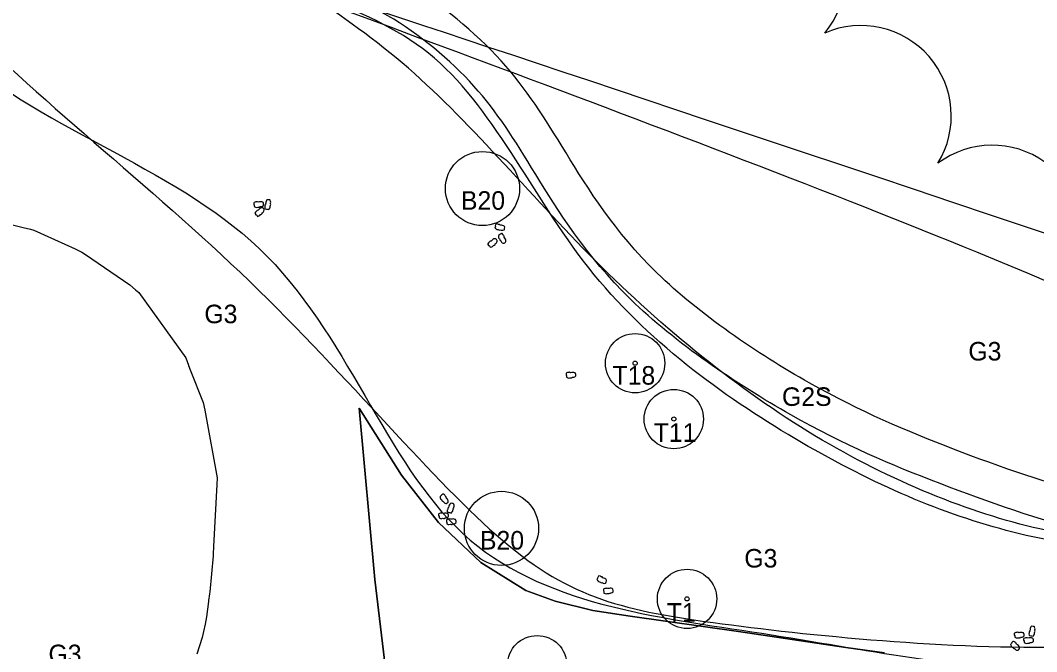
# Model space of a CAD drawing. Extents: x 0 to 512122, y 0 to 6212554.
# Drawn here: x 511501.5 to 511570.1, y 6211382.9 to 6211425.5 of the extents above; entities that cross this region are included whole.
import ezdxf

# ---------------------------------------------------------------- set-up
doc = ezdxf.new("R2010")
doc.units = 0
for name, color, linetype in [('_Marksten', 7, 'Continuous'), ('_Paths', 7, 'Continuous'), ('_S1_rabarber', 7, 'Continuous'), ('_Spredmingskorridor', 7, 'Continuous'), ('_Spredmingskorridor_hatch', 7, 'Continuous'), ('Clouds', 7, 'Continuous'), ('Skel', 7, 'Continuous'), ('TV_U_AFM_Symbl_Gul', 7, 'Continuous'), ('TV_U_LYS_Mastenummer', 7, 'Continuous'), ('TV_U_LYS_Nyx330-Trafiksti-x2', 7, 'Continuous')]:
    doc.layers.add(name, color=color, linetype=linetype)

# ---------------------------------------------------------------- blocks, each defined once
blk = doc.blocks.new('SOLITAIRE TREES')
at = {"layer": 'Skel'}
for radius in [2, 0.141]:
    blk.add_circle((0, 0), radius, dxfattribs=at)

msp = doc.modelspace()

# ---------------------------------------------------------------- linework, layer by layer
at = {"layer": '_Marksten'}
for points in [[(511517.3, 6211412.934), (511517.392, 6211412.896), (511517.449, 6211412.879), (511517.532, 6211412.902), (511517.597, 6211412.9), (511517.662, 6211412.898), (511517.696, 6211412.929), (511517.742, 6211412.932), (511517.803, 6211412.938), (511517.855, 6211412.959), (511517.921, 6211413.005), (511517.933, 6211413.037), (511517.932, 6211413.066), (511517.931, 6211413.11), (511517.914, 6211413.184), (511517.883, 6211413.222), (511517.852, 6211413.237), (511517.801, 6211413.253), (511517.731, 6211413.26), (511517.656, 6211413.245), (511517.579, 6211413.238), (511517.513, 6211413.264), (511517.454, 6211413.245), (511517.406, 6211413.248), (511517.366, 6211413.242), (511517.292, 6211413.214), (511517.272, 6211413.174), (511517.272, 6211413.088), (511517.301, 6211413.033)], [(511518.284, 6211412.742), (511518.344, 6211412.821), (511518.375, 6211412.873), (511518.374, 6211412.958), (511518.392, 6211413.02), (511518.411, 6211413.083), (511518.39, 6211413.124), (511518.398, 6211413.169), (511518.408, 6211413.23), (511518.4, 6211413.285), (511518.373, 6211413.361), (511518.345, 6211413.38), (511518.317, 6211413.387), (511518.274, 6211413.397), (511518.198, 6211413.399), (511518.154, 6211413.379), (511518.131, 6211413.353), (511518.103, 6211413.308), (511518.078, 6211413.241), (511518.073, 6211413.165), (511518.061, 6211413.089), (511518.019, 6211413.032), (511518.022, 6211412.97), (511518.008, 6211412.924), (511518.003, 6211412.884), (511518.011, 6211412.805), (511518.045, 6211412.776), (511518.128, 6211412.754), (511518.189, 6211412.768)], [(511517.522, 6211412.274), (511517.618, 6211412.299), (511517.673, 6211412.321), (511517.725, 6211412.389), (511517.778, 6211412.427), (511517.831, 6211412.465), (511517.839, 6211412.511), (511517.873, 6211412.541), (511517.919, 6211412.583), (511517.947, 6211412.632), (511517.971, 6211412.708), (511517.961, 6211412.741), (511517.943, 6211412.763), (511517.915, 6211412.797), (511517.857, 6211412.846), (511517.809, 6211412.857), (511517.776, 6211412.85), (511517.726, 6211412.832), (511517.665, 6211412.794), (511517.615, 6211412.737), (511517.558, 6211412.684), (511517.49, 6211412.666), (511517.455, 6211412.614), (511517.415, 6211412.587), (511517.386, 6211412.558), (511517.344, 6211412.491), (511517.354, 6211412.447), (511517.406, 6211412.379), (511517.463, 6211412.353)], [(511533.529, 6211411.487), (511533.605, 6211411.422), (511533.654, 6211411.389), (511533.739, 6211411.385), (511533.801, 6211411.363), (511533.862, 6211411.342), (511533.904, 6211411.36), (511533.949, 6211411.35), (511534.009, 6211411.336), (511534.065, 6211411.341), (511534.142, 6211411.364), (511534.163, 6211411.391), (511534.171, 6211411.418), (511534.183, 6211411.461), (511534.19, 6211411.536), (511534.172, 6211411.582), (511534.147, 6211411.606), (511534.104, 6211411.636), (511534.039, 6211411.665), (511533.963, 6211411.674), (511533.887, 6211411.69), (511533.833, 6211411.736), (511533.771, 6211411.736), (511533.726, 6211411.753), (511533.686, 6211411.76), (511533.607, 6211411.756), (511533.576, 6211411.724), (511533.55, 6211411.642), (511533.56, 6211411.58)], [(511533.757, 6211410.988), (511533.762, 6211410.888), (511533.772, 6211410.829), (511533.827, 6211410.765), (511533.854, 6211410.705), (511533.88, 6211410.645), (511533.922, 6211410.628), (511533.945, 6211410.588), (511533.977, 6211410.535), (511534.019, 6211410.497), (511534.088, 6211410.457), (511534.122, 6211410.461), (511534.148, 6211410.473), (511534.187, 6211410.494), (511534.246, 6211410.54), (511534.267, 6211410.585), (511534.268, 6211410.619), (511534.26, 6211410.672), (511534.236, 6211410.739), (511534.191, 6211410.8), (511534.151, 6211410.867), (511534.147, 6211410.937), (511534.104, 6211410.982), (511534.085, 6211411.027), (511534.063, 6211411.061), (511534.006, 6211411.116), (511533.961, 6211411.116), (511533.884, 6211411.079), (511533.846, 6211411.029)], [(511533.214, 6211410.203), (511533.311, 6211410.223), (511533.368, 6211410.242), (511533.423, 6211410.307), (511533.478, 6211410.342), (511533.533, 6211410.377), (511533.544, 6211410.422), (511533.58, 6211410.45), (511533.628, 6211410.489), (511533.658, 6211410.537), (511533.687, 6211410.611), (511533.679, 6211410.645), (511533.662, 6211410.668), (511533.636, 6211410.704), (511533.581, 6211410.755), (511533.534, 6211410.769), (511533.5, 6211410.764), (511533.449, 6211410.749), (511533.386, 6211410.715), (511533.333, 6211410.66), (511533.273, 6211410.611), (511533.204, 6211410.596), (511533.166, 6211410.547), (511533.125, 6211410.522), (511533.095, 6211410.495), (511533.049, 6211410.43), (511533.056, 6211410.386), (511533.104, 6211410.315), (511533.159, 6211410.285)], [(511538.349, 6211401.432), (511538.441, 6211401.393), (511538.499, 6211401.377), (511538.581, 6211401.399), (511538.646, 6211401.397), (511538.711, 6211401.395), (511538.746, 6211401.426), (511538.791, 6211401.43), (511538.853, 6211401.435), (511538.905, 6211401.457), (511538.97, 6211401.503), (511538.982, 6211401.535), (511538.982, 6211401.563), (511538.981, 6211401.607), (511538.964, 6211401.681), (511538.932, 6211401.72), (511538.902, 6211401.734), (511538.851, 6211401.75), (511538.78, 6211401.757), (511538.705, 6211401.743), (511538.628, 6211401.735), (511538.563, 6211401.762), (511538.503, 6211401.742), (511538.456, 6211401.745), (511538.415, 6211401.74), (511538.341, 6211401.712), (511538.322, 6211401.672), (511538.322, 6211401.586), (511538.351, 6211401.53)], [(511529.825, 6211393.398), (511529.842, 6211393.299), (511529.858, 6211393.242), (511529.921, 6211393.184), (511529.954, 6211393.128), (511529.987, 6211393.072), (511530.032, 6211393.06), (511530.059, 6211393.023), (511530.097, 6211392.974), (511530.143, 6211392.941), (511530.216, 6211392.91), (511530.25, 6211392.917), (511530.274, 6211392.933), (511530.31, 6211392.958), (511530.364, 6211393.011), (511530.379, 6211393.058), (511530.376, 6211393.092), (511530.362, 6211393.143), (511530.33, 6211393.207), (511530.278, 6211393.263), (511530.23, 6211393.324), (511530.218, 6211393.393), (511530.17, 6211393.433), (511530.147, 6211393.475), (511530.12, 6211393.506), (511530.058, 6211393.554), (511530.013, 6211393.549), (511529.94, 6211393.503), (511529.909, 6211393.449)], [(511530.569, 6211392.277), (511530.641, 6211392.346), (511530.68, 6211392.392), (511530.693, 6211392.476), (511530.721, 6211392.534), (511530.749, 6211392.593), (511530.734, 6211392.637), (511530.75, 6211392.68), (511530.77, 6211392.739), (511530.771, 6211392.795), (511530.756, 6211392.874), (511530.731, 6211392.898), (511530.705, 6211392.908), (511530.664, 6211392.925), (511530.59, 6211392.94), (511530.542, 6211392.927), (511530.516, 6211392.905), (511530.481, 6211392.864), (511530.446, 6211392.803), (511530.429, 6211392.728), (511530.405, 6211392.655), (511530.354, 6211392.606), (511530.347, 6211392.544), (511530.325, 6211392.501), (511530.314, 6211392.462), (511530.31, 6211392.383), (511530.339, 6211392.349), (511530.417, 6211392.314), (511530.48, 6211392.318)], [(511529.76, 6211391.95), (511529.852, 6211391.912), (511529.91, 6211391.895), (511529.992, 6211391.918), (511530.057, 6211391.916), (511530.122, 6211391.914), (511530.156, 6211391.945), (511530.202, 6211391.948), (511530.264, 6211391.953), (511530.316, 6211391.975), (511530.381, 6211392.021), (511530.393, 6211392.053), (511530.393, 6211392.081), (511530.391, 6211392.126), (511530.375, 6211392.2), (511530.343, 6211392.238), (511530.313, 6211392.253), (511530.262, 6211392.268), (511530.191, 6211392.276), (511530.116, 6211392.261), (511530.039, 6211392.253), (511529.974, 6211392.28), (511529.914, 6211392.261), (511529.867, 6211392.264), (511529.826, 6211392.258), (511529.752, 6211392.23), (511529.733, 6211392.19), (511529.733, 6211392.104), (511529.762, 6211392.049)], [(511530.279, 6211391.547), (511530.371, 6211391.509), (511530.429, 6211391.492), (511530.511, 6211391.515), (511530.576, 6211391.513), (511530.641, 6211391.511), (511530.675, 6211391.542), (511530.721, 6211391.546), (511530.783, 6211391.551), (511530.834, 6211391.572), (511530.9, 6211391.618), (511530.912, 6211391.65), (511530.911, 6211391.679), (511530.91, 6211391.723), (511530.893, 6211391.797), (511530.862, 6211391.835), (511530.831, 6211391.85), (511530.781, 6211391.866), (511530.71, 6211391.873), (511530.635, 6211391.858), (511530.558, 6211391.851), (511530.493, 6211391.877), (511530.433, 6211391.858), (511530.385, 6211391.861), (511530.345, 6211391.855), (511530.271, 6211391.827), (511530.251, 6211391.787), (511530.251, 6211391.701), (511530.281, 6211391.646)], [(511540.401, 6211387.792), (511540.461, 6211387.713), (511540.502, 6211387.669), (511540.584, 6211387.647), (511540.639, 6211387.612), (511540.694, 6211387.577), (511540.739, 6211387.587), (511540.781, 6211387.567), (511540.836, 6211387.54), (511540.892, 6211387.532), (511540.972, 6211387.538), (511540.999, 6211387.56), (511541.012, 6211387.585), (511541.034, 6211387.623), (511541.057, 6211387.696), (511541.049, 6211387.744), (511541.03, 6211387.773), (511540.995, 6211387.812), (511540.937, 6211387.854), (511540.865, 6211387.88), (511540.795, 6211387.912), (511540.753, 6211387.968), (511540.691, 6211387.982), (511540.652, 6211388.009), (511540.614, 6211388.024), (511540.536, 6211388.038), (511540.499, 6211388.013), (511540.455, 6211387.939), (511540.452, 6211387.877)], [(511540.87, 6211386.884), (511540.962, 6211386.846), (511541.019, 6211386.83), (511541.101, 6211386.852), (511541.166, 6211386.85), (511541.231, 6211386.848), (511541.266, 6211386.879), (511541.311, 6211386.883), (511541.373, 6211386.888), (511541.425, 6211386.91), (511541.491, 6211386.955), (511541.503, 6211386.988), (511541.502, 6211387.016), (511541.501, 6211387.06), (511541.484, 6211387.134), (511541.453, 6211387.172), (511541.422, 6211387.187), (511541.371, 6211387.203), (511541.3, 6211387.21), (511541.225, 6211387.196), (511541.148, 6211387.188), (511541.083, 6211387.215), (511541.024, 6211387.195), (511540.976, 6211387.198), (511540.935, 6211387.193), (511540.861, 6211387.165), (511540.842, 6211387.125), (511540.842, 6211387.039), (511540.871, 6211386.983)], [(511568.574, 6211383.905), (511568.666, 6211383.867), (511568.724, 6211383.851), (511568.806, 6211383.873), (511568.871, 6211383.871), (511568.936, 6211383.869), (511568.97, 6211383.9), (511569.016, 6211383.904), (511569.078, 6211383.909), (511569.129, 6211383.931), (511569.195, 6211383.976), (511569.207, 6211384.009), (511569.206, 6211384.037), (511569.205, 6211384.081), (511569.188, 6211384.155), (511569.157, 6211384.193), (511569.126, 6211384.208), (511569.076, 6211384.224), (511569.005, 6211384.231), (511568.93, 6211384.216), (511568.853, 6211384.209), (511568.788, 6211384.236), (511568.728, 6211384.216), (511568.68, 6211384.219), (511568.64, 6211384.213), (511568.566, 6211384.186), (511568.546, 6211384.145), (511568.546, 6211384.059), (511568.576, 6211384.004)], [(511569.817, 6211383.98), (511569.878, 6211384.059), (511569.909, 6211384.11), (511569.909, 6211384.195), (511569.928, 6211384.257), (511569.947, 6211384.32), (511569.927, 6211384.361), (511569.935, 6211384.406), (511569.947, 6211384.467), (511569.94, 6211384.522), (511569.913, 6211384.598), (511569.885, 6211384.618), (511569.858, 6211384.625), (511569.815, 6211384.635), (511569.739, 6211384.639), (511569.694, 6211384.619), (511569.671, 6211384.593), (511569.643, 6211384.548), (511569.617, 6211384.482), (511569.611, 6211384.406), (511569.598, 6211384.33), (511569.555, 6211384.274), (511569.558, 6211384.211), (511569.542, 6211384.166), (511569.537, 6211384.125), (511569.544, 6211384.047), (511569.578, 6211384.017), (511569.661, 6211383.995), (511569.722, 6211384.008)], [(511568.293, 6211383.423), (511568.329, 6211383.33), (511568.357, 6211383.277), (511568.429, 6211383.233), (511568.473, 6211383.185), (511568.516, 6211383.136), (511568.562, 6211383.132), (511568.596, 6211383.102), (511568.642, 6211383.06), (511568.694, 6211383.038), (511568.772, 6211383.022), (511568.804, 6211383.035), (511568.824, 6211383.055), (511568.855, 6211383.086), (511568.897, 6211383.149), (511568.903, 6211383.198), (511568.893, 6211383.231), (511568.87, 6211383.279), (511568.826, 6211383.335), (511568.764, 6211383.379), (511568.705, 6211383.43), (511568.68, 6211383.496), (511568.625, 6211383.526), (511568.594, 6211383.562), (511568.562, 6211383.588), (511568.491, 6211383.622), (511568.449, 6211383.609), (511568.386, 6211383.549), (511568.366, 6211383.49)], [(511569.201, 6211383.542), (511569.293, 6211383.504), (511569.35, 6211383.487), (511569.432, 6211383.51), (511569.497, 6211383.508), (511569.562, 6211383.506), (511569.597, 6211383.537), (511569.642, 6211383.54), (511569.704, 6211383.545), (511569.756, 6211383.567), (511569.822, 6211383.613), (511569.834, 6211383.645), (511569.833, 6211383.673), (511569.832, 6211383.718), (511569.815, 6211383.792), (511569.784, 6211383.83), (511569.753, 6211383.845), (511569.702, 6211383.86), (511569.631, 6211383.868), (511569.556, 6211383.853), (511569.479, 6211383.846), (511569.414, 6211383.872), (511569.355, 6211383.853), (511569.307, 6211383.856), (511569.266, 6211383.85), (511569.192, 6211383.822), (511569.173, 6211383.782), (511569.173, 6211383.696), (511569.202, 6211383.641)]]:
    msp.add_lwpolyline(points, close=True, dxfattribs=at)
at = {"layer": '_Paths'}
for points in [[(511619.187, 6211386.799), (511596.582, 6211393.479), (511585.389, 6211391.465), (511574.074, 6211393.08), (511564.353, 6211396.519), (511555.151, 6211400.37), (511543.395, 6211408.318), (511538.005, 6211417.069), (511534.527, 6211422.707), (511527.544, 6211428.597), (511520.899, 6211430.592), (511516.505, 6211433.059), (511513.01, 6211439.693), (511510.466, 6211444.112), (511507.781, 6211450.658), (511503.375, 6211454.994), (511500.203, 6211458.077), (511497.377, 6211464.569)], [(511614.911, 6211385.469), (511596.457, 6211390.915), (511585.439, 6211388.932), (511573.475, 6211390.64), (511563.453, 6211394.185), (511553.957, 6211398.16), (511541.549, 6211406.549), (511535.876, 6211415.757), (511532.609, 6211421.054), (511526.328, 6211426.352), (511519.916, 6211428.277), (511514.638, 6211431.24), (511510.82, 6211438.486), (511508.216, 6211443.009), (511505.662, 6211449.236), (511501.627, 6211453.206), (511498.108, 6211456.628), (511495.085, 6211463.571)]]:
    msp.add_open_spline(points, degree=3, dxfattribs=at)
at = {"layer": '_S1_rabarber'}
for points in [[(511526.256, 6211376.989), (511526.268, 6211380.857), (511525.432, 6211387.792), (511524.381, 6211399.347), (511527.219, 6211394.835), (511529.727, 6211391.636), (511532.584, 6211388.932), (511535.615, 6211387.042), (511537.588, 6211386.323), (511540.138, 6211385.706), (511542.64, 6211385.314), (511549.961, 6211384.291), (511557.192, 6211383.208), (511559.801, 6211382.854)], [(511559.801, 6211382.854), (511557.192, 6211383.208), (511549.961, 6211384.291), (511542.64, 6211385.314), (511540.138, 6211385.706), (511537.588, 6211386.323), (511535.615, 6211387.042), (511532.584, 6211388.932), (511529.727, 6211391.636), (511527.219, 6211394.835), (511524.381, 6211399.347), (511525.432, 6211387.792), (511526.268, 6211380.857), (511526.256, 6211376.989)]]:
    msp.add_lwpolyline(points, dxfattribs=at)
at = {"layer": '_Spredmingskorridor'}
for points in [[(511618.625, 6211420.62), (511606.029, 6211410.569), (511596.93, 6211398.178), (511583.32, 6211390.017), (511570.813, 6211390.175), (511555.007, 6211396.479), (511539.801, 6211408.822), (511527.664, 6211423.862), (511513.195, 6211431.425), (511508.403, 6211440.656), (511501.753, 6211451.707), (511492.266, 6211459.065), (511618.625, 6211420.62), (511492.266, 6211459.065)], [(511446.919, 6211452.593), (511459.024, 6211449.612), (511483.052, 6211444.239), (511494.738, 6211426.247), (511517.996, 6211408.457), (511535.129, 6211387.296), (511545.806, 6211384.873), (511574.749, 6211382.071), (511593.151, 6211386.596), (511609.301, 6211398.194), (511446.919, 6211452.593), (511609.301, 6211398.194)]]:
    msp.add_open_spline(points, degree=3, dxfattribs=at)
at = {"layer": '_Spredmingskorridor_hatch'}
for points in [[(511581.75, 6211389.913), (511577.7, 6211389.37), (511567.855, 6211390.317), (511554.005, 6211396.469), (511538.606, 6211407.597), (511530.73, 6211425.908), (511512.751, 6211428.394), (511508.404, 6211441.832), (511502.763, 6211452.312), (511495.709, 6211456.958), (511492.308, 6211459.197)], [(511467.291, 6211448.868), (511473.268, 6211448.326), (511486.519, 6211446.703), (511493.234, 6211420.769), (511520.952, 6211413.243), (511528.733, 6211386.924), (511552.285, 6211384.428), (511571.21, 6211380.366), (511589.487, 6211384.409), (511596.578, 6211388.532), (511598.184, 6211389.583)]]:
    msp.add_open_spline(points, degree=3, dxfattribs=at)
at = {"layer": 'Clouds'}
for centre, radius, start, end in [((511551.069, 6211428.524), 6.101, 320.37832, 105.37832), ((511558.199, 6211419.039), 6.1, 328.4855, 113.4855), ((511567.06, 6211410.971), 6.1, 341.87244, 126.87244)]:
    msp.add_arc(centre, radius, start, end, dxfattribs=at)
at = {"layer": 'TV_U_LYS_Mastenummer'}
for centre in [(511532.686, 6211414.148), (511532.686, 6211414.148), (511533.969, 6211391.243), (511533.969, 6211391.243)]:
    msp.add_circle(centre, 2.5, dxfattribs=at)
at = {"layer": 'TV_U_LYS_Nyx330-Trafiksti-x2'}
msp.add_lwpolyline([(511496.371, 6211412.864), (511501.725, 6211411.534), (511502.21, 6211411.401), (511502.428, 6211411.341), (511505.222, 6211410.081), (511505.673, 6211409.863), (511505.929, 6211409.71), (511508.916, 6211407.647), (511509.3, 6211407.326), (511509.509, 6211407.149), (511512.684, 6211402.744), (511512.859, 6211402.245), (511512.87, 6211402.214), (511512.967, 6211401.938), (511513.856, 6211399.737), (511513.967, 6211399.216), (511514.02, 6211398.966), (511514.788, 6211394.647), (511514.78, 6211394.2), (511514.546, 6211390.029), (511514.528, 6211389.521), (511514.525, 6211389.391), (511514.307, 6211386.966), (511514.305, 6211386.953), (511514.305, 6211386.951), (511514.305, 6211386.951), (511514.289, 6211386.85), (511514.274, 6211386.756), (511514.267, 6211386.711), (511514.265, 6211386.703), (511514.227, 6211386.465), (511514.222, 6211386.432), (511514.203, 6211386.311), (511514.089, 6211385.28), (511513.982, 6211384.782), (511513.874, 6211384.285), (511513.788, 6211383.886), (511513.427, 6211382.772)], dxfattribs=at)

# ---------------------------------------------------------------- block references
at = {"layer": 'Skel'}
for p in [(511542.98, 6211402.374), (511545.589, 6211398.609), (511546.48, 6211386.487), (511536.374, 6211382.017)]:
    msp.add_blockref('SOLITAIRE TREES', p, dxfattribs=at)

# ---------------------------------------------------------------- texts
at = {"layer": 'TV_U_AFM_Symbl_Gul'}
for s, p in [('B20', (511531.236, 6211412.72)), ('G3', (511513.935, 6211405.069)), ('G3', (511565.448, 6211402.557)), ('T18', (511541.455, 6211400.93)), ('G2S', (511552.883, 6211399.496)), ('T11', (511544.231, 6211397.074)), ('B20', (511532.519, 6211389.815)), ('G3', (511550.341, 6211388.6)), ('T1', (511545.122, 6211384.952)), ('G3', (511503.424, 6211382.153))]:
    msp.add_text(s, height=1.25, dxfattribs=at).set_placement(p)

doc.saveas('drawing.dxf')
